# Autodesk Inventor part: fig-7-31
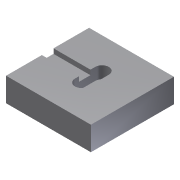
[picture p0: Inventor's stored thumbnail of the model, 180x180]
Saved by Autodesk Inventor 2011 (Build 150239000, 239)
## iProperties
Created: 2004-05
Part Number: fig-7-31
Document SubType Name: Modeling
Designer: CADCIM Technologies
Manufacturer: Standard
Standards Organization: Custom
Density: 1 g/cm^3
Author: CADCIM Technologies
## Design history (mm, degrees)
sketch "Sketch1"
  geometry: L1 (-30.233, -25.517)-(22.302, -25.517); L2 (22.302, -25.517)-(22.302, 25.904); L3 (22.302, 25.904)-(-30.233, 25.904); L4 (-30.233, 25.904)-(-30.233, -25.517)
  constraints: 8 end point, 2 parallel, 1 horizontal, 1 perpendicular
extrude "Extrusion1" new body sketch "Sketch1" distance "d0" = 14.75; taper "d1" = 0 deg
sketch "Sketch2"
  geometry: L1 (1.047, -5.75)-(1.047, 6.846); L2 (-7.35, 6.845)-(-7.35, -5.75); A1 r 4.198 centre (-3.152, 6.846) between (1.047, 6.846) and (-7.35, 6.845); A2 r 4.198 centre (-3.152, -5.75) between (-7.35, -5.75) and (1.047, -5.75)
  constraints: 4 end point, 4 point on circle, 4 tangent, 2 centre point, 1 parallel
extrude "Extrusion2" cut sketch "Sketch2" distance "d2" = 7.5; taper "d3" = 0 deg
sketch "Sketch3"
  geometry: L1 (-7.5, 0)-(-7.5, 12.595) reference; L2 (-7.5, 0)-(0, 0) reference; L3 (-7.5, 2.416)-(-4.537, 2.416); L4 (-4.537, 2.416)-(-4.537, 9.616); L5 (-4.537, 9.616)-(-7.5, 9.616)
  constraints: 6 end point, 2 perpendicular, 2 point on line, 1 parallel
extrude "Extrusion3" cut sketch "Sketch3" stored distance "d4" = 6.75; taper "d5" = 0 deg
body "Solid1"
